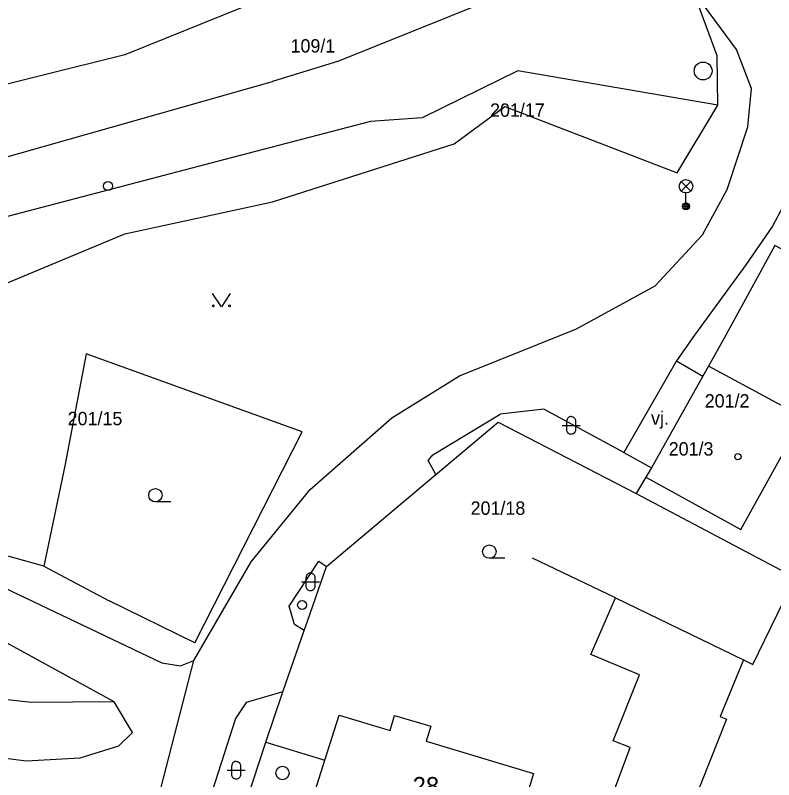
# Model space of a CAD drawing. Extents: x -836739 to -835945, y -1070775 to -1070126.
# Drawn here: x -836543.18 to -836500.64, y -1070362.36 to -1070319.51 of the extents above; entities that cross this region are included whole.
import ezdxf

# ---------------------------------------------------------------- set-up
doc = ezdxf.new("R2010")
doc.units = 0
for name, color, linetype in [('BodPole_mer', 7, 'Continuous'), ('Budovy_hranice', 7, 'Continuous'), ('Budovy_kody', 7, 'Continuous'), ('Doprava_hranice', 7, 'Continuous'), ('Doprava_kody', 7, 'Continuous'), ('OstPloch_kody', 7, 'Continuous'), ('PovrZnIS_body', 7, 'Continuous'), ('RuianAdr_popis', 7, 'Continuous'), ('RuianPar_popis', 7, 'Continuous'), ('Stavby_linie', 7, 'Continuous'), ('Zelen_kody', 7, 'Continuous')]:
    doc.layers.add(name, color=color, linetype=linetype)

msp = doc.modelspace()

# ---------------------------------------------------------------- linework, layer by layer
at = {"layer": 'BodPole_mer'}
for p, q in [((-836502.72, -1070321.42), (-836502.72, -1070321.42)), ((-836537.03, -1070321.73), (-836537.03, -1070321.73)), ((-836503.82, -1070321.79), (-836503.82, -1070321.79)), ((-836525.05, -1070322.08), (-836525.05, -1070322.08)), ((-836515, -1070322.63), (-836515, -1070322.63)), ((-836504.6, -1070322.63), (-836504.6, -1070322.63)), ((-836528.75, -1070323.23), (-836528.75, -1070323.23)), ((-836501.89, -1070323.62), (-836501.89, -1070323.62)), ((-836515.72, -1070324.62), (-836515.72, -1070324.62)), ((-836503.77, -1070324.55), (-836503.77, -1070324.55)), ((-836520.35, -1070325.26), (-836520.35, -1070325.26)), ((-836523.26, -1070325.47), (-836523.26, -1070325.47)), ((-836502.09, -1070325.77), (-836502.09, -1070325.77)), ((-836518.57, -1070326.72), (-836518.57, -1070326.72)), ((-836531.42, -1070327.59), (-836531.42, -1070327.59)), ((-836506.05, -1070328.35), (-836506.05, -1070328.35)), ((-836537.98, -1070329.08), (-836537.98, -1070329.08)), ((-836503.25, -1070329.28), (-836503.25, -1070329.28)), ((-836528.76, -1070329.97), (-836528.76, -1070329.97)), ((-836505.56, -1070330.22), (-836505.56, -1070330.22)), ((-836500.71, -1070331.34), (-836500.71, -1070331.34)), ((-836537.04, -1070331.76), (-836537.04, -1070331.76)), ((-836504.64, -1070331.81), (-836504.64, -1070331.81)), ((-836502.21, -1070333.5), (-836502.21, -1070333.5)), ((-836507.28, -1070334.68), (-836507.28, -1070334.68)), ((-836511.7, -1070337.08), (-836511.7, -1070337.08)), ((-836505.09, -1070337.45), (-836505.09, -1070337.45)), ((-836503.41, -1070337.61), (-836503.41, -1070337.61)), ((-836539.2, -1070338.48), (-836539.2, -1070338.48)), ((-836506.09, -1070338.88), (-836506.09, -1070338.88)), ((-836504.3, -1070339.18), (-836504.3, -1070339.18)), ((-836518.27, -1070339.72), (-836518.27, -1070339.72)), ((-836504.62, -1070339.74), (-836504.62, -1070339.74)), ((-836513.54, -1070341.59), (-836513.54, -1070341.59)), ((-836522.06, -1070342.08), (-836522.06, -1070342.08)), ((-836515.98, -1070341.87), (-836515.98, -1070341.87)), ((-836516.09, -1070342.31), (-836516.09, -1070342.31)), ((-836527.08, -1070342.86), (-836527.08, -1070342.86)), ((-836519.75, -1070344.15), (-836519.75, -1070344.15)), ((-836509.04, -1070344.01), (-836509.04, -1070344.01)), ((-836520.02, -1070344.47), (-836520.02, -1070344.47)), ((-836540.39, -1070344.76), (-836540.39, -1070344.76)), ((-836507.5, -1070344.87), (-836507.5, -1070344.87)), ((-836519.59, -1070345.25), (-836519.59, -1070345.25)), ((-836507.81, -1070345.41), (-836507.81, -1070345.41)), ((-836526.64, -1070346.09), (-836526.64, -1070346.09)), ((-836508.36, -1070346.32), (-836508.36, -1070346.32)), ((-836502.49, -1070348.34), (-836502.49, -1070348.34)), ((-836529.95, -1070350.14), (-836529.95, -1070350.14)), ((-836526.15, -1070350.11), (-836526.15, -1070350.11)), ((-836514.16, -1070349.95), (-836514.16, -1070349.95)), ((-836541.58, -1070350.39), (-836541.58, -1070350.39)), ((-836525.73, -1070350.4), (-836525.73, -1070350.4)), ((-836526.76, -1070351.04), (-836526.76, -1070351.04)), ((-836537.92, -1070352.34), (-836537.92, -1070352.34)), ((-836509.51, -1070352.17), (-836509.51, -1070352.17)), ((-836527.82, -1070352.64), (-836527.82, -1070352.64)), ((-836527.09, -1070352.57), (-836527.09, -1070352.57)), ((-836526.79, -1070353.47), (-836526.79, -1070353.47)), ((-836527.51, -1070353.66), (-836527.51, -1070353.66)), ((-836526.98, -1070354), (-836526.98, -1070354)), ((-836533.11, -1070354.69), (-836533.11, -1070354.69)), ((-836510.89, -1070355.34), (-836510.89, -1070355.34)), ((-836533.17, -1070355.68), (-836533.17, -1070355.68)), ((-836502.34, -1070355.64), (-836502.34, -1070355.64)), ((-836534.96, -1070355.81), (-836534.96, -1070355.81)), ((-836533.92, -1070355.97), (-836533.92, -1070355.97)), ((-836501.82, -1070355.9), (-836501.82, -1070355.9)), ((-836508.16, -1070356.49), (-836508.16, -1070356.49)), ((-836528.18, -1070357.44), (-836528.18, -1070357.44)), ((-836542.27, -1070358.03), (-836542.27, -1070358.03)), ((-836537.63, -1070358), (-836537.63, -1070358)), ((-836530.22, -1070358.03), (-836530.22, -1070358.03)), ((-836525.01, -1070358.74), (-836525.01, -1070358.74)), ((-836521.9, -1070358.76), (-836521.9, -1070358.76)), ((-836530.82, -1070358.93), (-836530.82, -1070358.93)), ((-836503.65, -1070358.81), (-836503.65, -1070358.81)), ((-836503.28, -1070358.96), (-836503.28, -1070358.96)), ((-836522.15, -1070359.6), (-836522.15, -1070359.6)), ((-836519.88, -1070359.35), (-836519.88, -1070359.35)), ((-836536.61, -1070359.71), (-836536.61, -1070359.71)), ((-836537.36, -1070360.46), (-836537.36, -1070360.46)), ((-836529.13, -1070360.25), (-836529.13, -1070360.25)), ((-836520.14, -1070360.2), (-836520.14, -1070360.2)), ((-836509.64, -1070360.18), (-836509.64, -1070360.18)), ((-836508.7, -1070360.55), (-836508.7, -1070360.55)), ((-836542.56, -1070361.3), (-836542.56, -1070361.3)), ((-836539.53, -1070361.13), (-836539.53, -1070361.13)), ((-836525.81, -1070361.26), (-836525.81, -1070361.26)), ((-836514.12, -1070362.01), (-836514.12, -1070362.01))]:
    msp.add_line(p, q, dxfattribs=at)
at = {"layer": 'Budovy_hranice'}
msp.add_line((-836507.81, -1070345.41), (-836502.49, -1070348.34), dxfattribs=at)
for points in [[(-836504.3, -1070339.18), (-836504.62, -1070339.74), (-836507.5, -1070344.87), (-836507.81, -1070345.41)], [(-836502.49, -1070348.34), (-836498.99, -1070342.03), (-836504.3, -1070339.18)], [(-836506.52, -1070367.12), (-836507.53, -1070366.76), (-836509.49, -1070372.86), (-836517.87, -1070370.16), (-836527.63, -1070367.01), (-836525.81, -1070361.26), (-836525.01, -1070358.74), (-836522.15, -1070359.6), (-836521.9, -1070358.76), (-836519.88, -1070359.35), (-836520.14, -1070360.2), (-836514.12, -1070362.01), (-836514.92, -1070364.66), (-836510.71, -1070366), (-836508.7, -1070360.55), (-836509.64, -1070360.18), (-836508.16, -1070356.49), (-836510.89, -1070355.34), (-836509.51, -1070352.17), (-836502.34, -1070355.64), (-836503.65, -1070358.81), (-836503.28, -1070358.96), (-836506.52, -1070367.12)]]:
    msp.add_lwpolyline(points, dxfattribs=at)
at = {"layer": 'Budovy_kody'}
msp.add_circle((-836502.65, -1070344.25), 0.175, dxfattribs=at)
at = {"layer": 'Doprava_hranice'}
for p, q in [((-836561.92, -1070332.6), (-836528.75, -1070323.23)), ((-836506.09, -1070338.88), (-836504.62, -1070339.74)), ((-836509.04, -1070344.01), (-836507.5, -1070344.87))]:
    msp.add_line(p, q, dxfattribs=at)
for points in [[(-836473.79, -1070281.33), (-836483.18, -1070291.85), (-836486.04, -1070295.25), (-836496.69, -1070306.07), (-836498.64, -1070308.92), (-836508.98, -1070315.34), (-836516.87, -1070318.79), (-836525.05, -1070322.08), (-836528.75, -1070323.23)], [(-836486.39, -1070290.44), (-836498.54, -1070302.85), (-836505.49, -1070308.01), (-836514.78, -1070313.23), (-836530.36, -1070319.04), (-836537.03, -1070321.73), (-836555.38, -1070326.29), (-836561.14, -1070327.96), (-836562.04, -1070328.06)], [(-836536.4, -1070368.21), (-836533.17, -1070355.68), (-836529.95, -1070350.14), (-836526.64, -1070346.09), (-836522.06, -1070342.08), (-836518.27, -1070339.72), (-836511.7, -1070337.08), (-836507.28, -1070334.68), (-836504.64, -1070331.81), (-836503.25, -1070329.28), (-836502.09, -1070325.77), (-836501.89, -1070323.62), (-836502.72, -1070321.42), (-836505.15, -1070318.12), (-836506.77, -1070316.06), (-836508.98, -1070315.34)], [(-836541.58, -1070350.39), (-836544.34, -1070349.63), (-836547.79, -1070346.93), (-836549.07, -1070344.38), (-836548.75, -1070338.43), (-836546.32, -1070335.63), (-836537.04, -1070331.76), (-836528.76, -1070329.97), (-836518.57, -1070326.72), (-836515.72, -1070324.62), (-836506.05, -1070328.35), (-836503.77, -1070324.55), (-836503.82, -1070321.79), (-836505.15, -1070318.12)], [(-836503.77, -1070324.55), (-836515, -1070322.63), (-836520.35, -1070325.26), (-836523.26, -1070325.47), (-836531.42, -1070327.59), (-836546.27, -1070331.48), (-836550.47, -1070335.93), (-836551.89, -1070339.77), (-836552.03, -1070343.83), (-836551.31, -1070347.61)], [(-836456.49, -1070361.78), (-836456.25, -1070359.46), (-836459.92, -1070355.96), (-836465.33, -1070351.01), (-836472.65, -1070344.35), (-836480.74, -1070337.07), (-836490.99, -1070328.59), (-836496.17, -1070324.43), (-836496.72, -1070324.41), (-836497.13, -1070324.67), (-836498.53, -1070327.13), (-836499.22, -1070328.53), (-836500.71, -1070331.34), (-836502.21, -1070333.5), (-836505.09, -1070337.45), (-836506.09, -1070338.88), (-836509.04, -1070344.01), (-836513.54, -1070341.59), (-836515.98, -1070341.87)], [(-836561.92, -1070332.6), (-836562.29, -1070333.46), (-836559.69, -1070338.29), (-836553.98, -1070345.27), (-836551.31, -1070347.61), (-836545.02, -1070351.03), (-836534.96, -1070355.81), (-836533.92, -1070355.97), (-836533.17, -1070355.68)], [(-836615.19, -1070379.26), (-836605.62, -1070372.23), (-836598.73, -1070367.69), (-836589.69, -1070363.97), (-836577.99, -1070361.29), (-836567.54, -1070359.78), (-836561.76, -1070359.47), (-836555.57, -1070359.6), (-836542.56, -1070361.3), (-836539.53, -1070361.13), (-836537.36, -1070360.46), (-836536.61, -1070359.71), (-836537.63, -1070358), (-836543.83, -1070354.6), (-836550.65, -1070351.53), (-836553.41, -1070349.94), (-836556.85, -1070346.77), (-836557.71, -1070345.9), (-836560.14, -1070342.4), (-836564.87, -1070335.97), (-836569.41, -1070333.94)], [(-836519.59, -1070345.25), (-836520.02, -1070344.47), (-836519.75, -1070344.15), (-836515.98, -1070341.87)], [(-836526.98, -1070354), (-836527.51, -1070353.66), (-836527.82, -1070352.64), (-836526.76, -1070351.04), (-836526.15, -1070350.11), (-836525.73, -1070350.4)], [(-836537.63, -1070358), (-836542.27, -1070358.03), (-836548.18, -1070357.38), (-836559.01, -1070354.67), (-836562.23, -1070356.44)], [(-836528.18, -1070357.44), (-836530.22, -1070358.03), (-836530.82, -1070358.93), (-836533.08, -1070365.97), (-836532.53, -1070367.2), (-836531.39, -1070367.56)]]:
    msp.add_lwpolyline(points, dxfattribs=at)
at = {"layer": 'OstPloch_kody'}
for p, q in [((-836512.5, -1070342.5), (-836511.5, -1070342.5)), ((-836512.25, -1070342.75), (-836512.25, -1070342.25)), ((-836511.75, -1070342.25), (-836511.75, -1070342.75)), ((-836534.445, -1070346.79), (-836535.32, -1070346.79)), ((-836515.715, -1070349.95), (-836516.59, -1070349.95)), ((-836526.87, -1070351.52), (-836526.87, -1070351.02)), ((-836526.37, -1070351.02), (-836526.37, -1070351.52)), ((-836527.12, -1070351.27), (-836526.12, -1070351.27)), ((-836531.04, -1070362.08), (-836531.04, -1070361.58)), ((-836530.54, -1070361.58), (-836530.54, -1070362.08)), ((-836531.29, -1070361.83), (-836530.29, -1070361.83))]:
    msp.add_line(p, q, dxfattribs=at)
for points in [[(-836512, -1070342), (-836512.045, -1070342.004), (-836512.092, -1070342.018), (-836512.137, -1070342.041), (-836512.177, -1070342.073), (-836512.209, -1070342.113), (-836512.232, -1070342.158), (-836512.246, -1070342.205), (-836512.25, -1070342.25)], [(-836512, -1070342), (-836511.955, -1070342.004), (-836511.908, -1070342.018), (-836511.863, -1070342.041), (-836511.823, -1070342.073), (-836511.791, -1070342.113), (-836511.768, -1070342.158), (-836511.754, -1070342.205), (-836511.75, -1070342.25)], [(-836512, -1070343), (-836512.045, -1070342.996), (-836512.092, -1070342.982), (-836512.137, -1070342.959), (-836512.177, -1070342.927), (-836512.209, -1070342.887), (-836512.232, -1070342.842), (-836512.246, -1070342.795), (-836512.25, -1070342.75)], [(-836511.75, -1070342.75), (-836511.754, -1070342.795), (-836511.768, -1070342.842), (-836511.791, -1070342.887), (-836511.823, -1070342.927), (-836511.863, -1070342.959), (-836511.908, -1070342.982), (-836511.955, -1070342.996), (-836512, -1070343)], [(-836526.62, -1070350.77), (-836526.665, -1070350.774), (-836526.712, -1070350.788), (-836526.757, -1070350.811), (-836526.797, -1070350.843), (-836526.829, -1070350.883), (-836526.852, -1070350.928), (-836526.866, -1070350.975), (-836526.87, -1070351.02)], [(-836526.62, -1070350.77), (-836526.575, -1070350.774), (-836526.528, -1070350.788), (-836526.483, -1070350.811), (-836526.443, -1070350.843), (-836526.411, -1070350.883), (-836526.388, -1070350.928), (-836526.374, -1070350.975), (-836526.37, -1070351.02)], [(-836526.62, -1070351.77), (-836526.665, -1070351.766), (-836526.712, -1070351.752), (-836526.757, -1070351.729), (-836526.797, -1070351.697), (-836526.829, -1070351.657), (-836526.852, -1070351.612), (-836526.866, -1070351.565), (-836526.87, -1070351.52)], [(-836526.37, -1070351.52), (-836526.374, -1070351.565), (-836526.388, -1070351.612), (-836526.411, -1070351.657), (-836526.443, -1070351.697), (-836526.483, -1070351.729), (-836526.528, -1070351.752), (-836526.575, -1070351.766), (-836526.62, -1070351.77)], [(-836530.79, -1070361.33), (-836530.835, -1070361.334), (-836530.882, -1070361.348), (-836530.927, -1070361.371), (-836530.967, -1070361.403), (-836530.999, -1070361.443), (-836531.022, -1070361.488), (-836531.036, -1070361.535), (-836531.04, -1070361.58)], [(-836530.79, -1070361.33), (-836530.745, -1070361.334), (-836530.698, -1070361.348), (-836530.653, -1070361.371), (-836530.613, -1070361.403), (-836530.581, -1070361.443), (-836530.558, -1070361.488), (-836530.544, -1070361.535), (-836530.54, -1070361.58)], [(-836530.79, -1070362.33), (-836530.835, -1070362.326), (-836530.882, -1070362.312), (-836530.927, -1070362.289), (-836530.967, -1070362.257), (-836530.999, -1070362.217), (-836531.022, -1070362.172), (-836531.036, -1070362.125), (-836531.04, -1070362.08)], [(-836530.54, -1070362.08), (-836530.544, -1070362.125), (-836530.558, -1070362.172), (-836530.581, -1070362.217), (-836530.613, -1070362.257), (-836530.653, -1070362.289), (-836530.698, -1070362.312), (-836530.745, -1070362.326), (-836530.79, -1070362.33)]]:
    msp.add_lwpolyline(points, dxfattribs=at)
for centre in [(-836535.32, -1070346.415), (-836516.59, -1070349.575), (-836528.19, -1070361.985)]:
    msp.add_ellipse(centre, major_axis=(0.375, 0), ratio=0.999999, dxfattribs=at)
at = {"layer": 'PovrZnIS_body'}
for p, q in [((-836505.825, -1070329.36), (-836505.295, -1070328.83)), ((-836505.825, -1070328.83), (-836505.295, -1070329.36)), ((-836505.56, -1070330.02), (-836505.56, -1070329.47))]:
    msp.add_line(p, q, dxfattribs=at)
for centre, radius in [((-836504.6, -1070322.63), 0.5), ((-836537.98, -1070329.08), 0.25), ((-836527.09, -1070352.57), 0.25)]:
    msp.add_circle(centre, radius, dxfattribs=at)
for centre, major_axis in [((-836505.56, -1070329.095), (0.375, 0)), ((-836505.56, -1070330.22), (0.2, 0)), ((-836505.556, -1070330.22), (0.125, 0)), ((-836505.556, -1070330.22), (0.05, 0))]:
    msp.add_ellipse(centre, major_axis=major_axis, ratio=0.999998, dxfattribs=at)
at = {"layer": 'RuianPar_popis'}
for p, q in [((-836527.74, -1070321.6), (-836527.74, -1070321.6)), ((-836516.55, -1070325.2), (-836516.55, -1070325.2)), ((-836504.51, -1070341.5), (-836504.51, -1070341.5)), ((-836540.24, -1070342.49), (-836540.24, -1070342.49)), ((-836506.53, -1070344.19), (-836506.53, -1070344.19)), ((-836517.64, -1070347.51), (-836517.64, -1070347.51))]:
    msp.add_line(p, q, dxfattribs=at)
at = {"layer": 'Stavby_linie'}
for p, q in [((-836503.41, -1070337.61), (-836504.3, -1070339.18)), ((-836507.81, -1070345.41), (-836508.36, -1070346.32)), ((-836508.36, -1070346.32), (-836499.44, -1070351.03)), ((-836509.51, -1070352.17), (-836514.16, -1070349.95)), ((-836526.79, -1070353.47), (-836525.73, -1070350.4)), ((-836533.11, -1070354.69), (-836537.92, -1070352.34)), ((-836529.13, -1070360.25), (-836525.81, -1070361.26))]:
    msp.add_line(p, q, dxfattribs=at)
for points in [[(-836493.1, -1070336.59), (-836496.65, -1070334.47), (-836500.57, -1070332.42), (-836503.41, -1070337.61)], [(-836502.34, -1070355.64), (-836501.82, -1070355.9), (-836499.44, -1070351.03), (-836494.05, -1070339.35), (-836493.01, -1070337.1)], [(-836533.11, -1070354.69), (-836527.08, -1070342.86), (-836539.2, -1070338.48), (-836540.39, -1070344.76), (-836541.58, -1070350.39), (-836537.92, -1070352.34)], [(-836525.73, -1070350.4), (-836519.59, -1070345.25), (-836516.09, -1070342.31), (-836508.36, -1070346.32)], [(-836528.18, -1070357.44), (-836526.98, -1070354), (-836526.79, -1070353.47)], [(-836530.96, -1070365.85), (-836529.13, -1070360.25), (-836528.18, -1070357.44)]]:
    msp.add_lwpolyline(points, dxfattribs=at)
at = {"layer": 'Zelen_kody'}
msp.add_lwpolyline([(-836531.12, -1070335.1), (-836531.62, -1070335.85), (-836532.12, -1070335.1)], dxfattribs=at)
for centre in [(-836532.069, -1070335.8), (-836531.169, -1070335.8)]:
    msp.add_circle(centre, 0.05, dxfattribs=at)

# ---------------------------------------------------------------- texts
at = {"layer": 'Doprava_kody'}
msp.add_text('vj.', height=0.75, dxfattribs=at).set_placement((-836507.52, -1070342.46))
at = {"layer": 'RuianAdr_popis'}
msp.add_text('28', height=1, dxfattribs=at).set_placement((-836520.89, -1070363.21))
at = {"layer": 'RuianPar_popis'}
for s, p in [('109/1', (-836527.74, -1070321.6)), ('201/17', (-836516.55, -1070325.2)), ('201/2', (-836504.51, -1070341.5)), ('201/15', (-836540.24, -1070342.49)), ('201/3', (-836506.53, -1070344.19)), ('201/18', (-836517.64, -1070347.51))]:
    msp.add_text(s, height=0.75, dxfattribs=at).set_placement(p)

doc.saveas('drawing.dxf')
